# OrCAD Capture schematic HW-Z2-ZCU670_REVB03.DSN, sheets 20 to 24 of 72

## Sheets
20 020 USB 3.0: size Custom
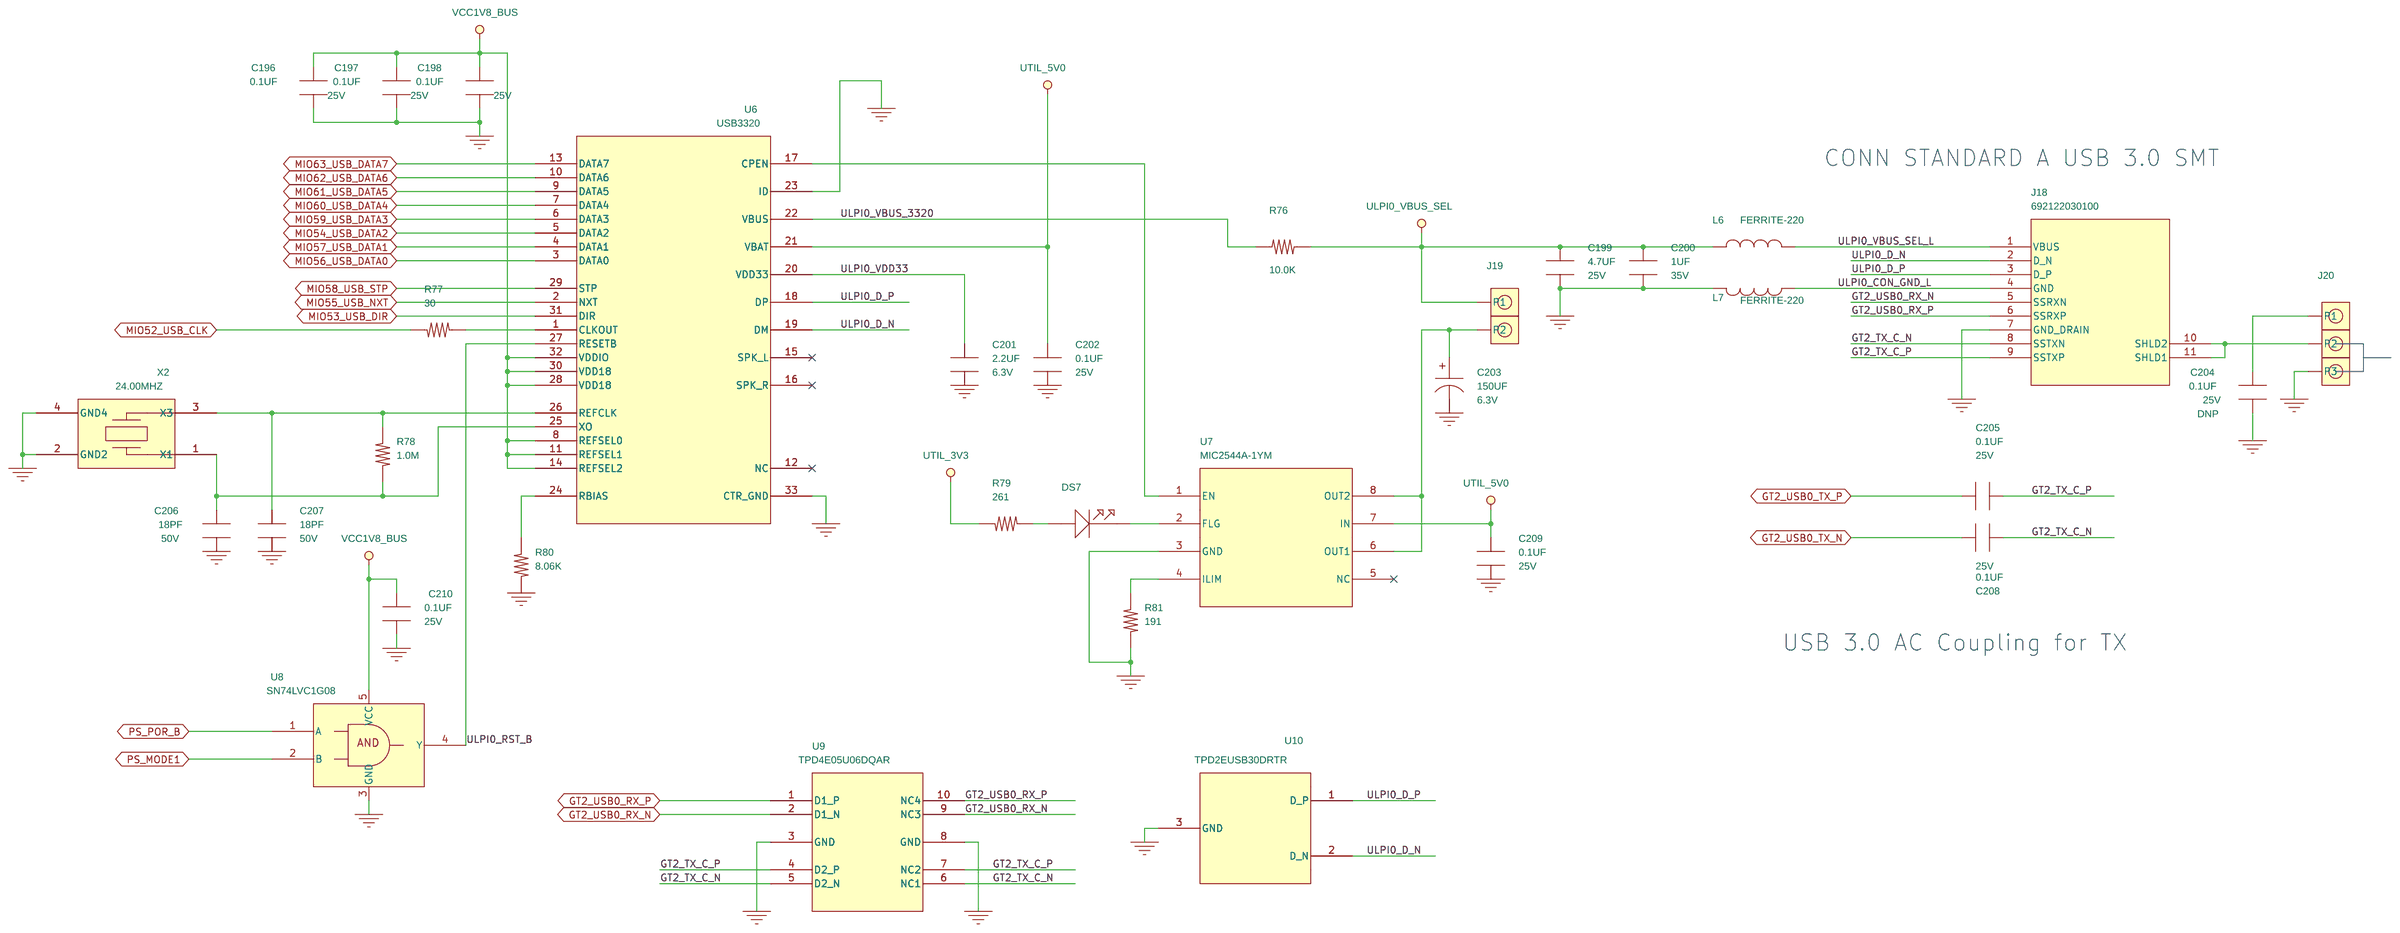
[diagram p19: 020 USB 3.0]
21 021 Dual QSPI: size Custom
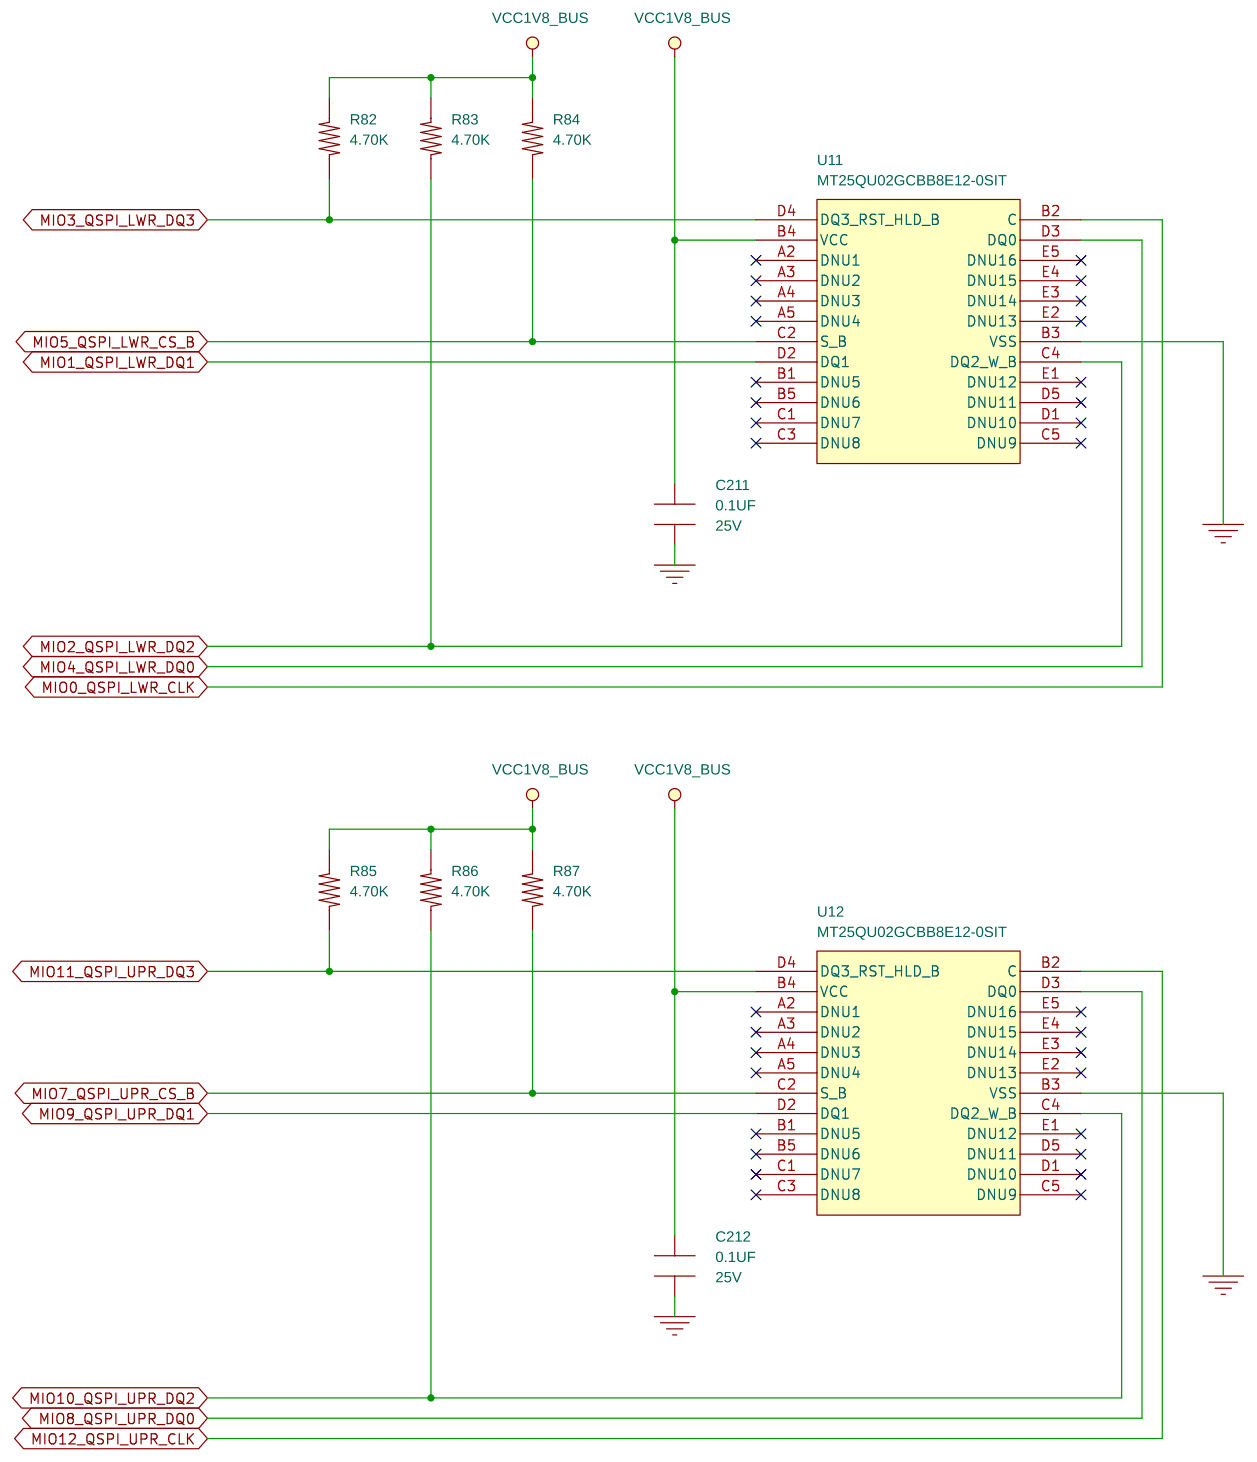
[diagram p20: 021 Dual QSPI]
22 022 I2C0: size Custom
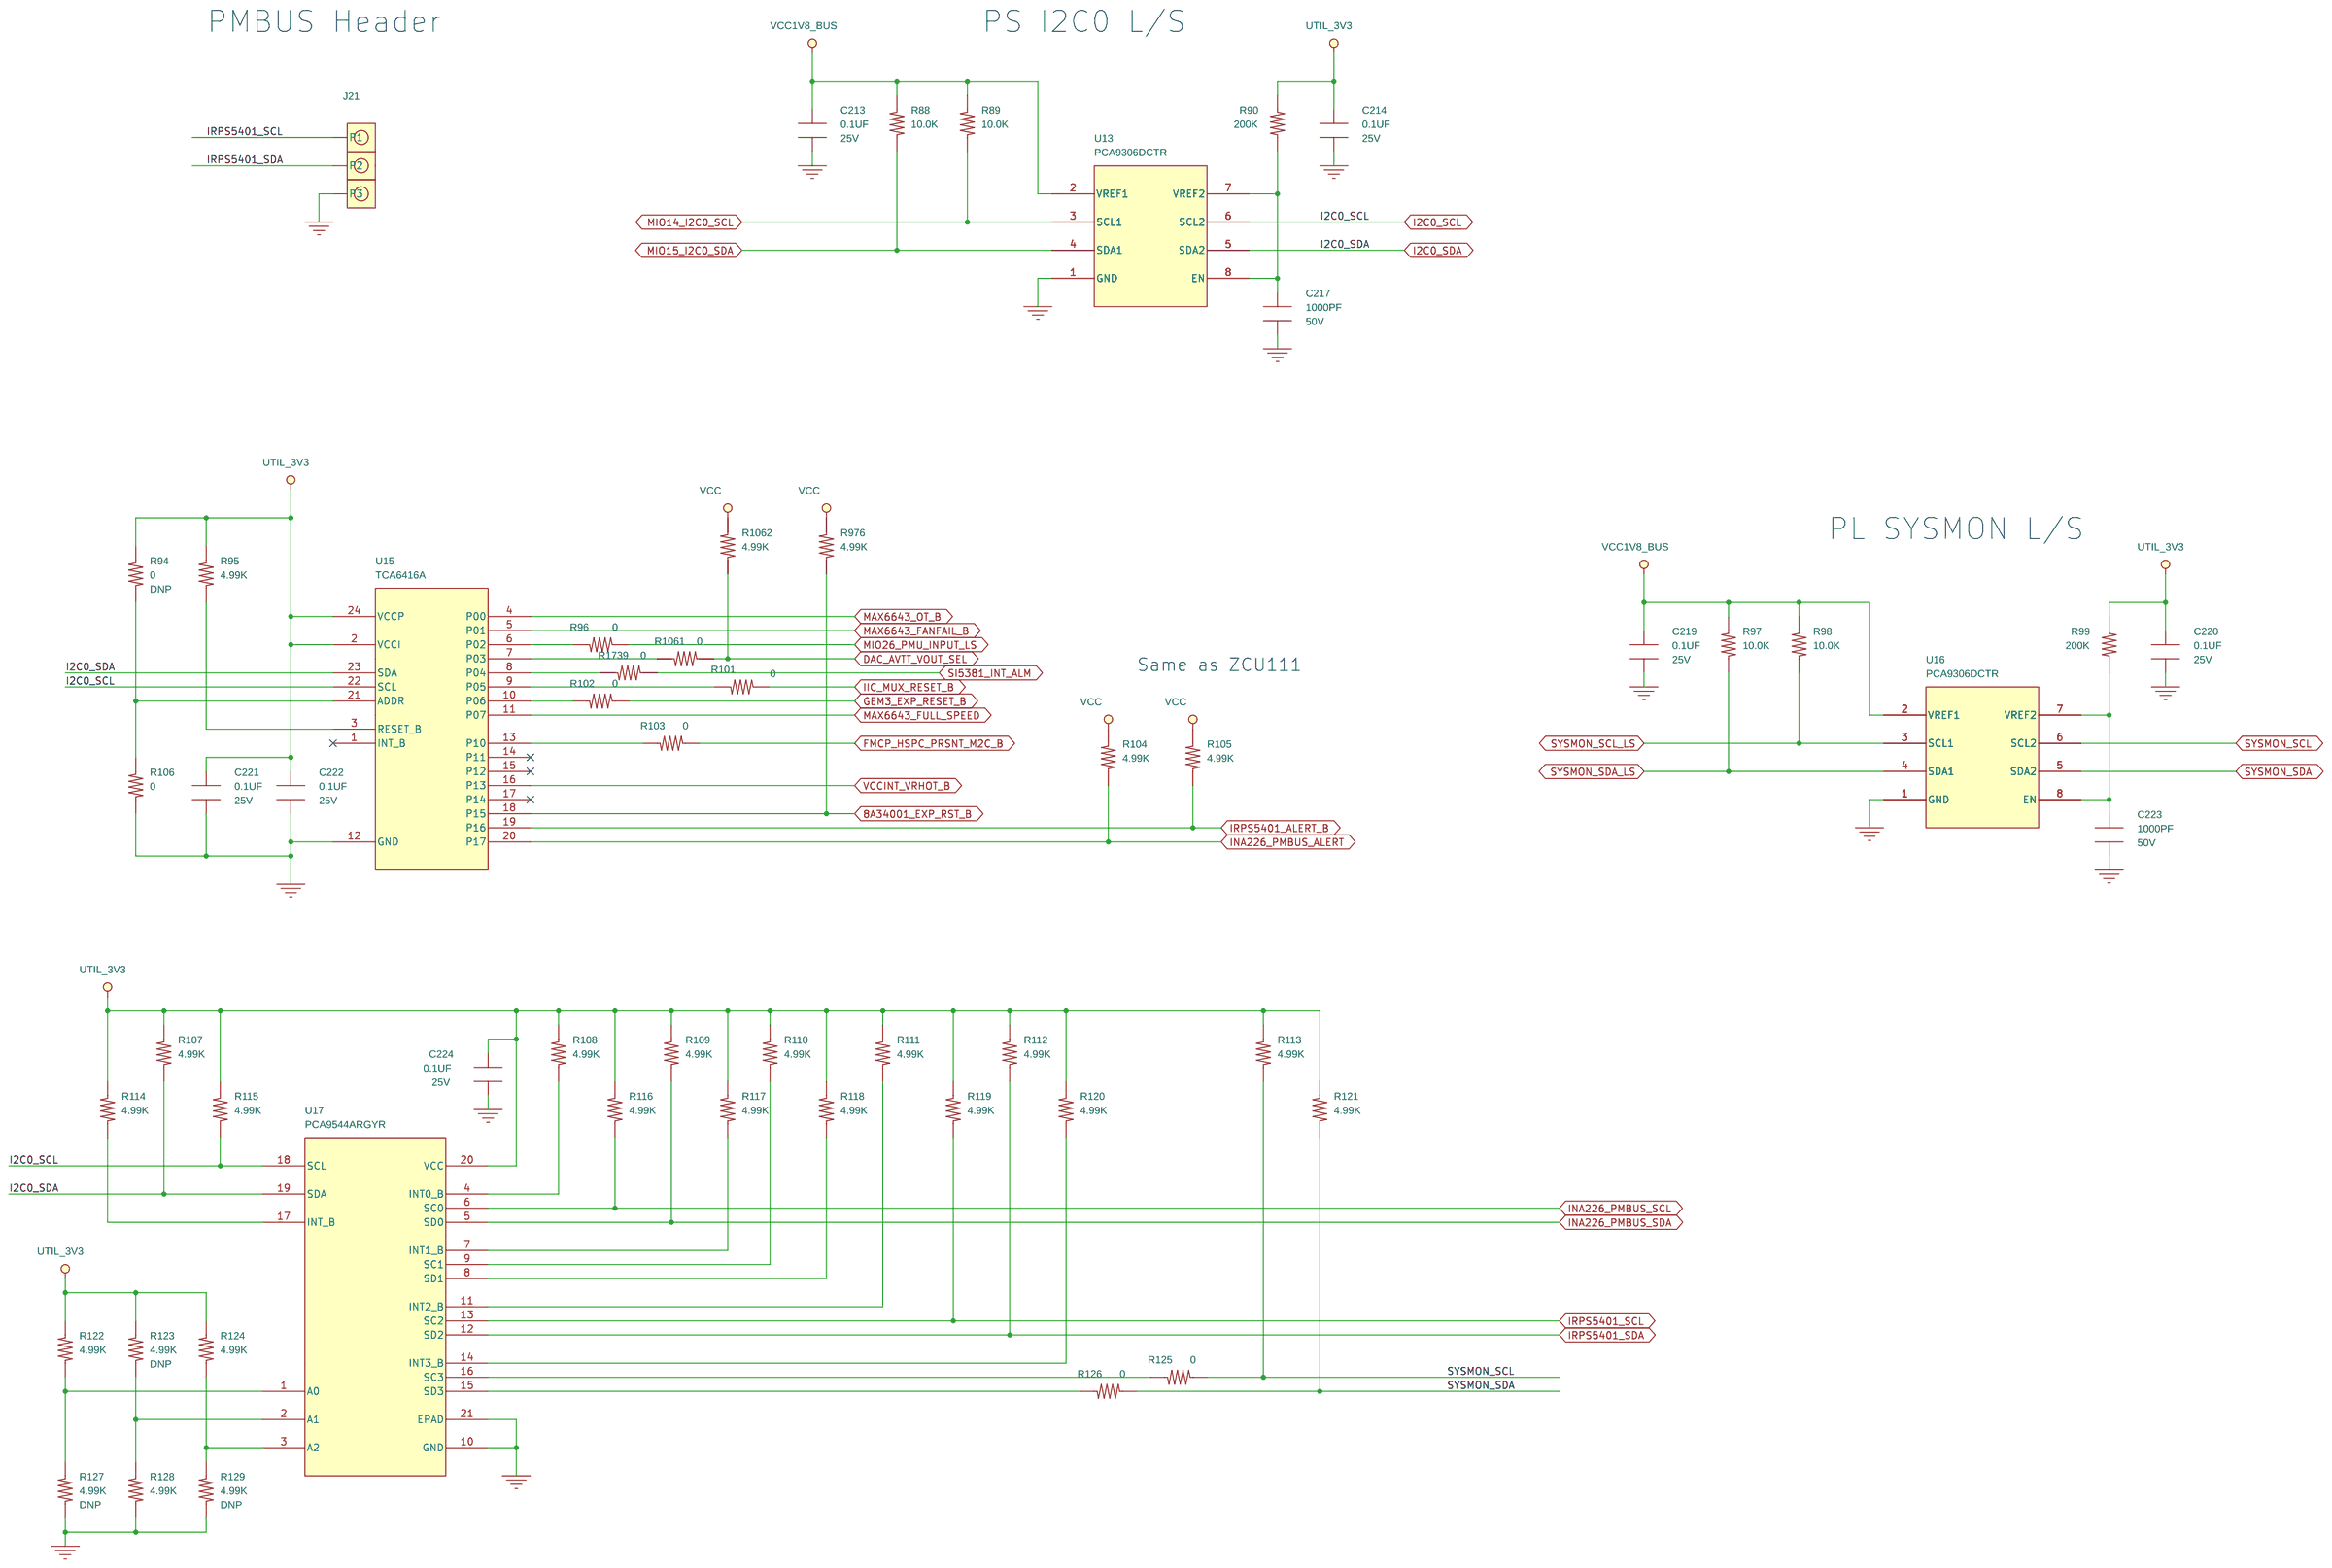
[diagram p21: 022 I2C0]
23 023 I2C1: size Custom
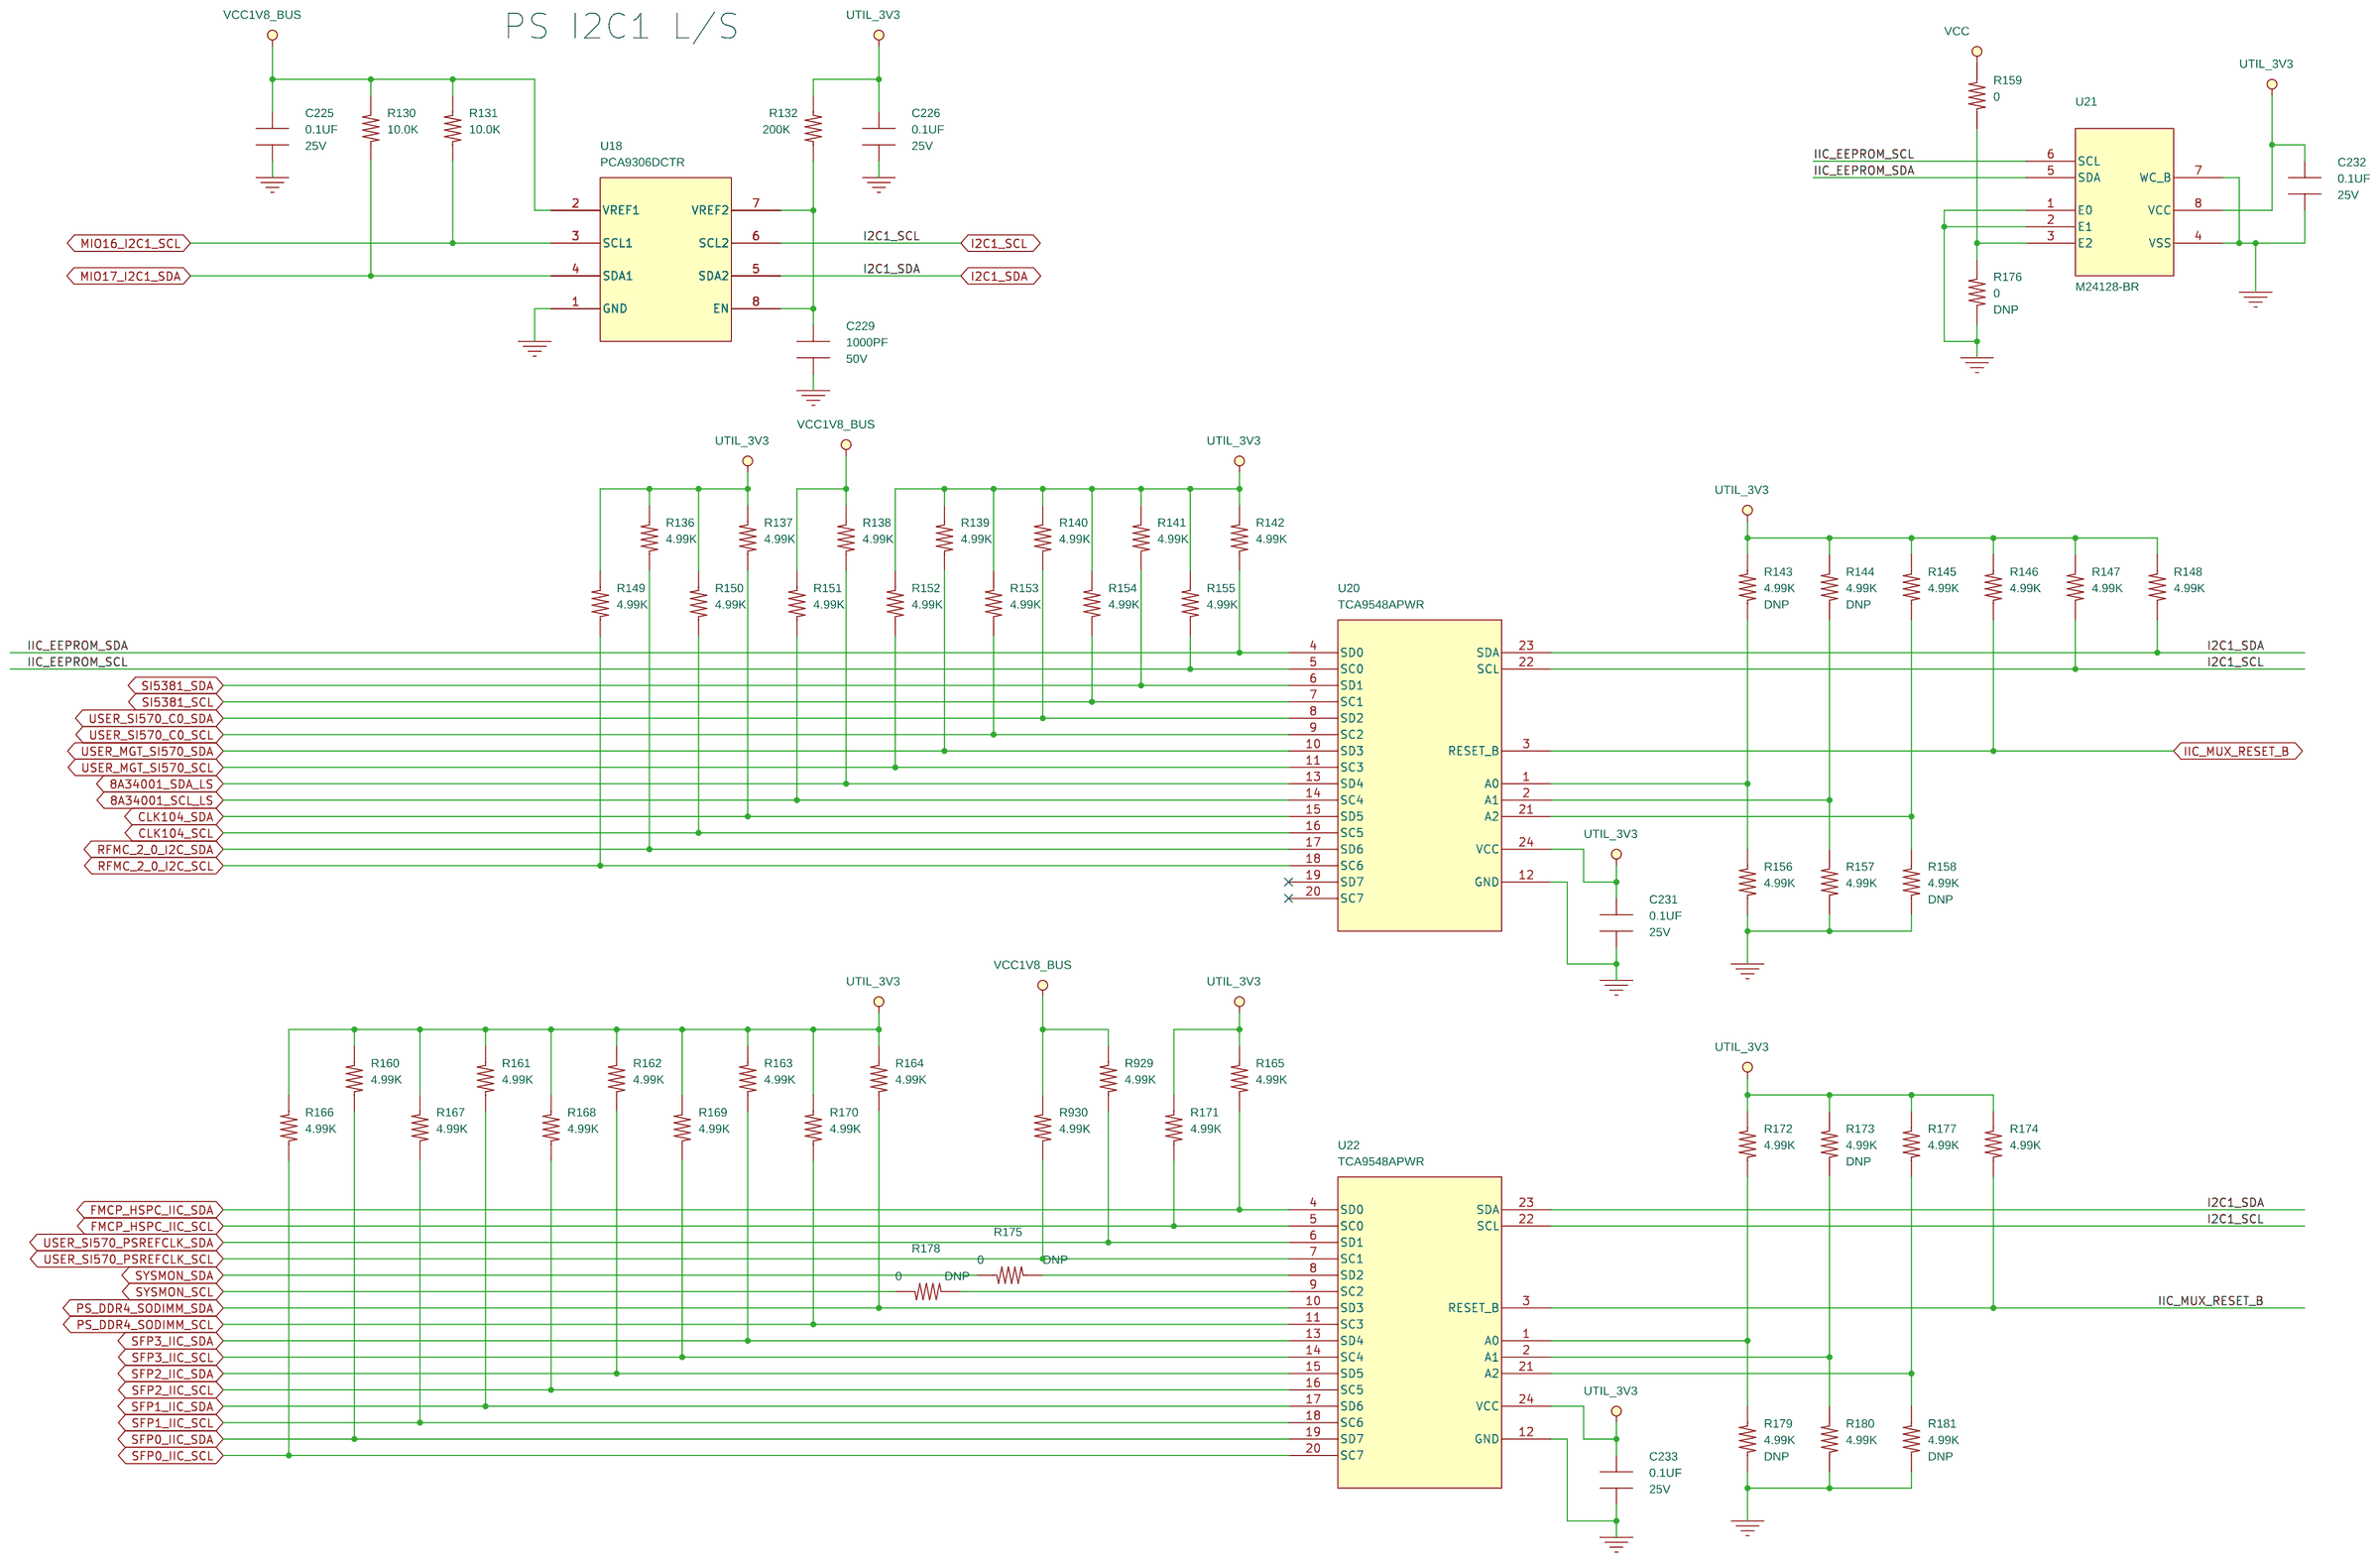
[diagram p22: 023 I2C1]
24 024 SD 3.0: size Custom
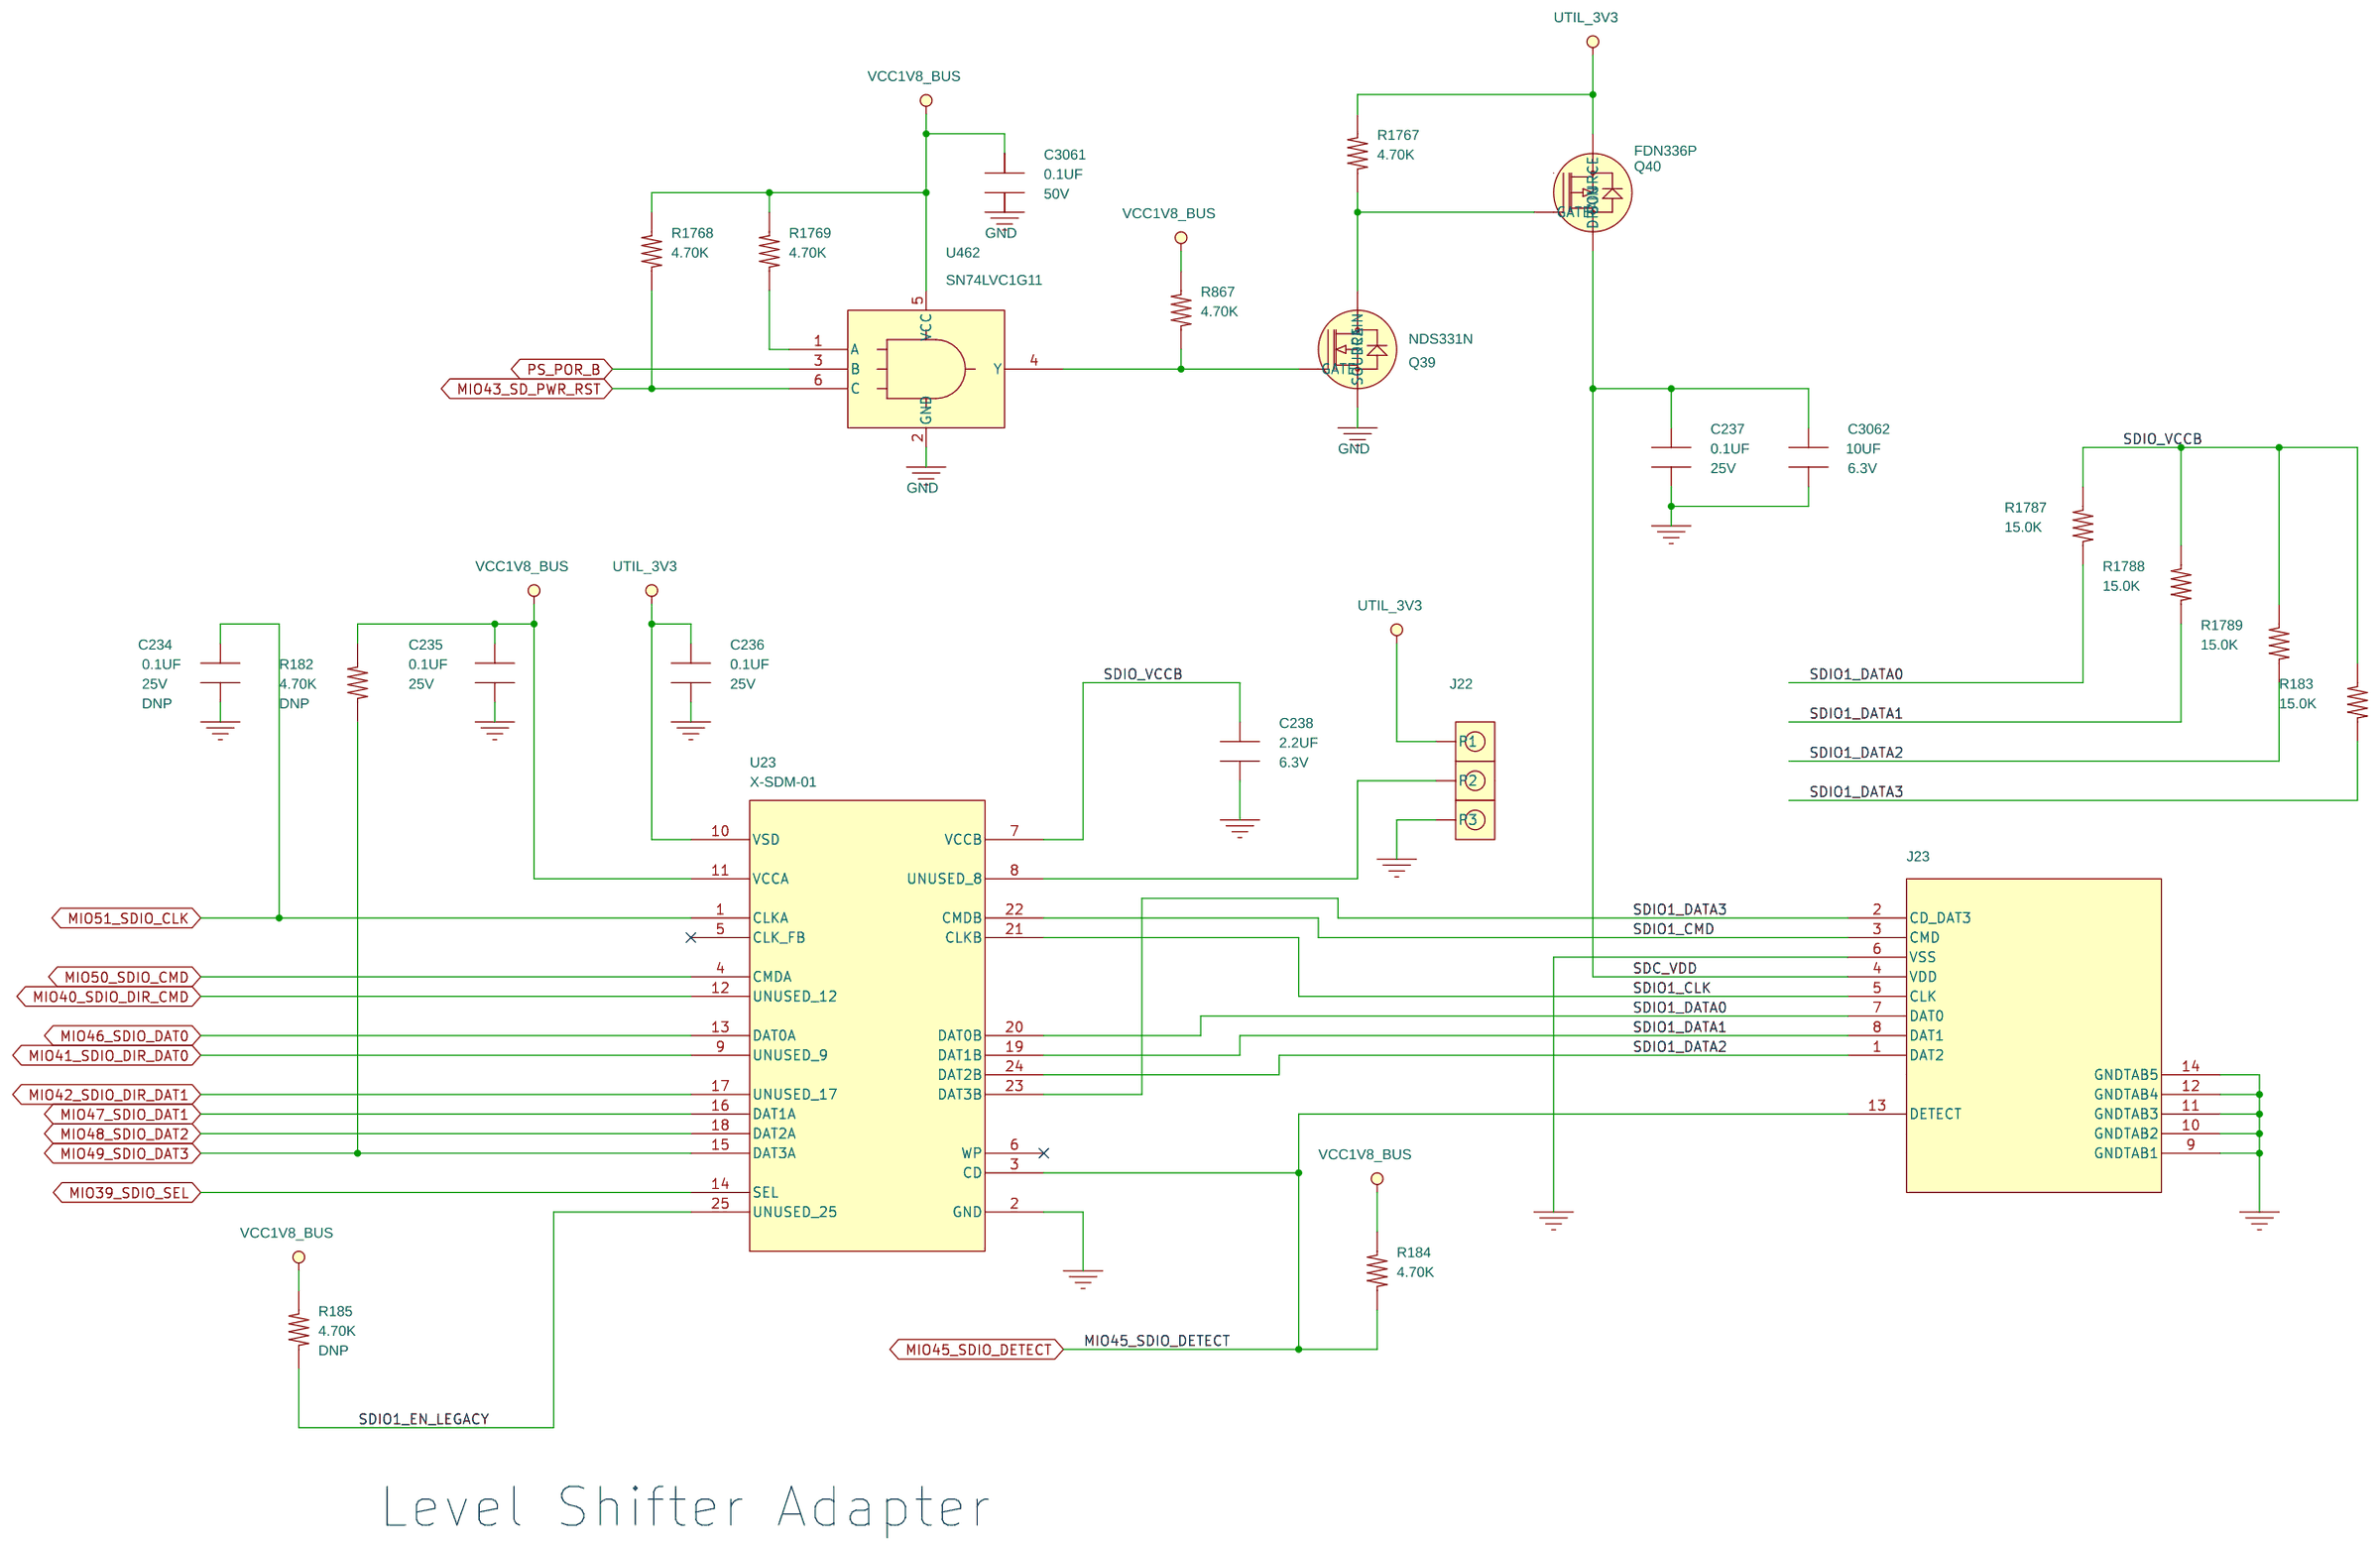
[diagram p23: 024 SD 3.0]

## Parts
sheet 020 USB 3.0
C196  0.1UF  [CAPC100X50X55]
C197  0.1UF  [CAPC100X50X55]
C198  0.1UF  [CAPC100X50X55]
C199  4.7UF  [CAPC160X80X100]
C200  1UF  [CAPC100X50X60]
C201  2.2UF  [CAPC100X50X55]
C202  0.1UF  [CAPC100X50X55]
C203  150UF  [CAPMP730X430X210]
C204  0.1UF  [CAPC100X50X55]
C205  0.1UF  [CAPC100X50X55]
C206  18PF  [CAPC100X50X50]
C207  18PF  [CAPC100X50X50]
C208  0.1UF  [CAPC100X50X55]
C209  0.1UF  [CAPC100X50X55]
C210  0.1UF  [CAPC100X50X55]
DS7  LED-GRN-SMT  [LED_0603]
J18  692122030100  [CON_CNC_692122030100]
J19  HDR_1X2  [HDR_1X2]
J20  HDR_1X3  [HDR_1X3]
L6  FERRITE-220  [INDC160X80X95]
L7  FERRITE-220  [INDC160X80X95]
R76  10.0K  [RESC100X50X40]
R77  30  [RESC100X50X40]
R78  1.0M  [RESC100X50X40]
R79  261  [RESC100X50X40]
R80  8.06K  [RESC100X50X40]
R81  191  [RESC100X50X40]
U6  USB3320  [QFN05P500X500X100_32P_330EP]
U7  MIC2544A-1YM  [SOIC_8]
U8  SN74LVC1G08  [SC70_5]
U9  TPD4E05U06DQAR  [DQA_R_PSON_N10]
U10  TPD2EUSB30DRTR  [DRT_R_PDSO_N3]
X2  24.00MHZ  [XTAL_EPSON_FA238]
sheet 021 Dual QSPI
C211  0.1UF  [CAPC100X50X55]
C212  0.1UF  [CAPC100X50X55]
R82  4.70K  [RESC100X50X40]
R83  4.70K  [RESC100X50X40]
R84  4.70K  [RESC100X50X40]
R85  4.70K  [RESC100X50X40]
R86  4.70K  [RESC100X50X40]
R87  4.70K  [RESC100X50X40]
U11  MT25QU02GCBB8E12-0SIT  [TPBGA_24_5X5]
U12  MT25QU02GCBB8E12-0SIT  [TPBGA_24_5X5]
sheet 022 I2C0
C213  0.1UF  [CAPC100X50X55]
C214  0.1UF  [CAPC100X50X55]
C217  1000PF  [CAPC100X50X55]
C219  0.1UF  [CAPC100X50X55]
C220  0.1UF  [CAPC100X50X55]
C221  0.1UF  [CAPC100X50X55]
C222  0.1UF  [CAPC100X50X55]
C223  1000PF  [CAPC100X50X55]
C224  0.1UF  [CAPC100X50X55]
J21  HDR_1X3  [HDR_1X3]
R88  10.0K  [RESC100X50X40]
R89  10.0K  [RESC100X50X40]
R90  200K  [RESC100X50X40]
R94  0  [RESC100X50X40]
R95  4.99K  [RESC100X50X40]
R96  0  [RESC100X50X40]
R97  10.0K  [RESC100X50X40]
R98  10.0K  [RESC100X50X40]
R99  200K  [RESC100X50X40]
R101  0  [RESC100X50X40]
R102  0  [RESC100X50X40]
R103  0  [RESC100X50X40]
R104  4.99K  [RESC100X50X40]
R105  4.99K  [RESC100X50X40]
R106  0  [RESC100X50X40]
R107  4.99K  [RESC100X50X40]
R108  4.99K  [RESC100X50X40]
R109  4.99K  [RESC100X50X40]
R110  4.99K  [RESC100X50X40]
R111  4.99K  [RESC100X50X40]
R112  4.99K  [RESC100X50X40]
R113  4.99K  [RESC100X50X40]
R114  4.99K  [RESC100X50X40]
R115  4.99K  [RESC100X50X40]
R116  4.99K  [RESC100X50X40]
R117  4.99K  [RESC100X50X40]
R118  4.99K  [RESC100X50X40]
R119  4.99K  [RESC100X50X40]
R120  4.99K  [RESC100X50X40]
R121  4.99K  [RESC100X50X40]
R122  4.99K  [RESC100X50X40]
R123  4.99K  [RESC100X50X40]
R124  4.99K  [RESC100X50X40]
R125  0  [RESC100X50X40]
R126  0  [RESC100X50X40]
R127  4.99K  [RESC100X50X40]
R128  4.99K  [RESC100X50X40]
R129  4.99K  [RESC100X50X40]
R976  4.99K  [RESC100X50X40]
R1061  0  [RESC100X50X40]
R1062  4.99K  [RESC100X50X40]
R1739  0  [RESC100X50X40]
U13  PCA9306DCTR  [DCT_R_PDSO_G8]
U15  TCA6416A  [TSSOP_24]
U16  PCA9306DCTR  [DCT_R_PDSO_G8]
U17  PCA9544ARGYR  [VQFN05P350x450x100_20_300X200]
sheet 023 I2C1
C225  0.1UF  [CAPC100X50X55]
C226  0.1UF  [CAPC100X50X55]
C229  1000PF  [CAPC100X50X55]
C231  0.1UF  [CAPC100X50X55]
C232  0.1UF  [CAPC100X50X55]
C233  0.1UF  [CAPC100X50X55]
R130  10.0K  [RESC100X50X40]
R131  10.0K  [RESC100X50X40]
R132  200K  [RESC100X50X40]
R136  4.99K  [RESC100X50X40]
R137  4.99K  [RESC100X50X40]
R138  4.99K  [RESC100X50X40]
R139  4.99K  [RESC100X50X40]
R140  4.99K  [RESC100X50X40]
R141  4.99K  [RESC100X50X40]
R142  4.99K  [RESC100X50X40]
R143  4.99K  [RESC100X50X40]
R144  4.99K  [RESC100X50X40]
R145  4.99K  [RESC100X50X40]
R146  4.99K  [RESC100X50X40]
R147  4.99K  [RESC100X50X40]
R148  4.99K  [RESC100X50X40]
R149  4.99K  [RESC100X50X40]
R150  4.99K  [RESC100X50X40]
R151  4.99K  [RESC100X50X40]
R152  4.99K  [RESC100X50X40]
R153  4.99K  [RESC100X50X40]
R154  4.99K  [RESC100X50X40]
R155  4.99K  [RESC100X50X40]
R156  4.99K  [RESC100X50X40]
R157  4.99K  [RESC100X50X40]
R158  4.99K  [RESC100X50X40]
R159  0  [RESC100X50X40]
R160  4.99K  [RESC100X50X40]
R161  4.99K  [RESC100X50X40]
R162  4.99K  [RESC100X50X40]
R163  4.99K  [RESC100X50X40]
R164  4.99K  [RESC100X50X40]
R165  4.99K  [RESC100X50X40]
R166  4.99K  [RESC100X50X40]
R167  4.99K  [RESC100X50X40]
R168  4.99K  [RESC100X50X40]
R169  4.99K  [RESC100X50X40]
R170  4.99K  [RESC100X50X40]
R171  4.99K  [RESC100X50X40]
R172  4.99K  [RESC100X50X40]
R173  4.99K  [RESC100X50X40]
R174  4.99K  [RESC100X50X40]
R175  0  [RESC100X50X40]
R176  0  [RESC100X50X40]
R177  4.99K  [RESC100X50X40]
R178  0  [RESC100X50X40]
R179  4.99K  [RESC100X50X40]
R180  4.99K  [RESC100X50X40]
R181  4.99K  [RESC100X50X40]
R929  4.99K  [RESC100X50X40]
R930  4.99K  [RESC100X50X40]
U18  PCA9306DCTR  [DCT_R_PDSO_G8]
U20  TCA9548APWR  [TSSOP_24]
U21  M24128-BR  [TSSOP65P640X120_8]
U22  TCA9548APWR  [TSSOP_24]
sheet 024 SD 3.0
C234  0.1UF  [CAPC100X50X55]
C235  0.1UF  [CAPC100X50X55]
C236  0.1UF  [CAPC100X50X55]
C237  0.1UF  [CAPC100X50X55]
C238  2.2UF  [CAPC100X50X55]
C3061  0.1UF  [CAPC100X50X55]
C3062  10UF  [CAPC100X50X70]
J22  HDR_1X3  [HDR_1X3]
J23  CON_MOL_10P_5025700893  [CON_MOL_10P_5025700893]
Q39  NDS331N  [SOT_23]
Q40  FDN336P  [SOT_23]
R182  4.70K  [RESC100X50X40]
R183  15.0K  [RESC100X50X40]
R184  4.70K  [RESC100X50X40]
R185  4.70K  [RESC100X50X40]
R867  4.70K  [RESC100X50X40]
R1767  4.70K  [RESC100X50X40]
R1768  4.70K  [RESC100X50X40]
R1769  4.70K  [RESC100X50X40]
R1787  15.0K  [RESC100X50X40]
R1788  15.0K  [RESC100X50X40]
R1789  15.0K  [RESC100X50X40]
U23  X-SDM-01  [IP4856CX25_SHIFTER_ADAPTER]
U462  SN74LVC1G11  [SC70_6]

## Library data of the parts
C196-C198 C202 C205 C208-C214 C219-C222 C224-C226 C231-C233 C235-C237 = CAP_NP: Cap Cer 100nF 10% 25V X5R 0402; ALT_SYMBOLS: CAPC100X50X55RND; Agile Part Number: CAP-00068-01; CIP Link: http://xsjbrdwin1/CIP-E/Component/Index/All?pn=100040; Dielectric Type: X5R; OWNER: 4001; PRICE: 0.01; Part Type: CERAMIC; PartType: CERAMIC; ROHS: Yes; Tolerance: 10%; Voltage: 25V; barcode: 100040
C199 = CAP_NP: Cap Cer 4.7uF 10% 25V X5R 0603; ALT_SYMBOLS: 0603; Agile Part Number: CAP-00182-01; CIP Link: http://xsjbrdwin1/CIP-E/Component/Index/All?pn=100220; Dielectric Type: X5R; OWNER: 8251; PRICE: 0.26; Part Type: CERAMIC; PartType: CERAMIC; ROHS: Yes; Tolerance: 10%; Voltage: 25V; barcode: 100220
C200 = CAP_NP: Cap Cer 1uF 10% 35V X5R 0402; ALT_SYMBOLS: CAPC100X50X60RND; Agile Part Number: CAP-00165-01; CIP Link: http://xsjbrdwin1/CIP-E/Component/Index/All?pn=100192; Dielectric Type: X5R; OWNER: 3709; PRICE: 0.04; Part Type: CERAMIC; PartType: CERAMIC; ROHS: Yes; Tolerance: 10%; Voltage: 35V; barcode: 100192
C201 C238 = CAP_NP: Cap Cer 2.2uF 20% 6.3V X5R 0402; Agile Part Number: CAP-00081-01; CIP Link: http://xsjbrdwin1/CIP-E/Component/Index/All?pn=100062; Dielectric Type: X5R; OWNER: 6176; PRICE: 0.06; Part Type: CERAMIC; PartType: CERAMIC; ROHS: Yes; Tolerance: 20%; Voltage: 6.3V; barcode: 100062
C203 = CAP_P: Cap Poly 150uF 20% 6.3V 12mR 7343; Agile Part Number: CAP-00157-01; CIP Link: http://xsjbrdwin1/CIP-E/Component/Index/All?pn=100183; Dielectric Type: SP; ESR: 12mohms; Equivalent Series Resistance: 12mohms; OWNER: 3709; PRICE: 0.68; Part Type: SPCAP; PartType: SPCAP; ROHS: Yes; Tolerance: 20%; Voltage: 6.3V; barcode: 100183
C204 C234 = CAP_NP: Cap Cer 100nF 10% 25V X5R 0402; ALT_SYMBOLS: CAPC100X50X55RND; ASSEMBLY_OPTIONS: DNP; Agile Part Number: CAP-00068-01; CIP Link: http://xsjbrdwin1/CIP-E/Component/Index/All?pn=100040; Dielectric Type: X5R; OWNER: 3709; PRICE: 0; Part Type: CERAMIC; PartType: CERAMIC; ROHS: Yes; Tolerance: 10%; Voltage: 25V; barcode: 100040
C206 C207 = CAP_NP: Cap Cer 18pF 2% 50% C0G 0402; ALT_SYMBOLS: CAPC100X50X50RND; Agile Part Number: CAP-00084-01; CIP Link: http://xsjbrdwin1/CIP-E/Component/Index/All?pn=100065; Dielectric Type: NPO; OWNER: 3709; PRICE: 0; Part Type: CERAMIC; PartType: CERAMIC; ROHS: Yes; Tolerance: 5%; Voltage: 50V; barcode: 100065
DS7 = LED: LED Green Diffused 20mA 5V 570nm 0603; Agile Part Number: DIO-00003-01; Barcode: 300021; CIP Link: http://xsjbrdwin1/CIP-E/Component/Index/All?pn=300021; OWNER: 4001; PRICE: 0.1; Power: 2.2-20MA; ROHS: Yes; Rated Power: 2.2-20MA; Voltage: 2.2V
J18 = 692122030100: Conn Rcpt USB 3.0 Type A RA 9 Pos 1x9 1.25mm P Blue SMT; Agile Part Number: CON-00183-01; Barcode: 400128; CIP Link: http://xsjbrdwin1/CIP-E/Component/Index/All?pn=400128; OWNER: 14196; PRICE: 2.4; Part Type: RECEPTACLE; PartType: RECEPTACLE; Pins: 9PINS; ROHS: Yes
J19 = HDR_1X2: Conn Hdr Male Vert 2 Pos 1x2 2.54mm P Black TH; Agile Part Number: CON-00037-01; Barcode: 390102; CIP Link: http://xsjbrdwin1/CIP-E/Component/Index/All?pn=390102; OWNER: 4001; PRICE: 0.03; Part Type: HEADER; PartType: HEADER; Pins: 2PINS; Pitch: 0.100; ROHS: Yes
J20-J22 = HDR_1X3: Conn Hdr Vert 3 Pos 1x3 2.54mm P Black TH; Agile Part Number: CON-00038-01; Barcode: 390103; CIP Link: http://xsjbrdwin1/CIP-E/Component/Index/All?pn=390103; Part Type: HEADER; Pitch: 0.100; ROHS: Yes
L6 L7 = IND: Bead 220R 25% 2A 50mR 0603; Agile Part Number: IND-00016-01; Barcode: 300010; CIP Link: http://xsjbrdwin1/CIP-E/Component/Index/All?pn=300010; OWNER: 4001; PRICE: 0.02; Part Type: FERRITE; PartType: FERRITE; ROHS: Yes
R76 R88 R89 R97 R98 R130 R131 = RES: Res 10K 1% 1/16W 100PPM 50V 0402; ALT_SYMBOLS: RESC100X50X40RND; Agile Part Number: RES-00030-01; Barcode: 200025; CIP Link: http://xsjbrdwin1/CIP-E/Component/Index/All?pn=200025; OWNER: 4001; PRICE: 0; Part Type: SMT - 1%; PartType: SMT - 1%; Power: 1/10W; ROHS: Yes; Rated Power: 1/16W; Tolerance: 1%; primarykey: 1
R77 = RES: Res 30R 1% 1/16W 100PPM 50V 0402; Agile Part Number: RES-00143-01; Barcode: 200133; CIP Link: http://xsjbrdwin1/CIP-E/Component/Index/All?pn=200133; OWNER: 3709; PRICE: 0; Part Type: SMT - 1%; PartType: SMT - 1%; Power: 1/10W; ROHS: Yes; Rated Power: 1/16W; Tolerance: 1%; primarykey: 93
R78 = RES: Res 1M 5% 1/16W 200PPM 50V 0402; Agile Part Number: RES-00066-01; Barcode: 200013; CIP Link: http://xsjbrdwin1/CIP-E/Component/Index/All?pn=200013; OWNER: 4001; PRICE: 0; Part Type: SMT - 5%; PartType: SMT - 5%; Power: 1/10W; ROHS: Yes; Rated Power: 1/16W; Tolerance: 5%; primarykey: 4
R79 = RES: Res 261R 1% 1/16W 100PPM 50V 0402; ALT_SYMBOLS: RESC100X50X40RND; Agile Part Number: RES-00086-01; Barcode: 200050; CIP Link: http://xsjbrdwin1/CIP-E/Component/Index/All?pn=200050; OWNER: 3501; PRICE: 0; Part Type: SMT - 1%; PartType: SMT - 1%; Power: 1/10W; ROHS: Yes; Rated Power: 1/16W; Tolerance: 1%; primarykey: 60
R80 = RES: Res 8K06 1% 1/16W 100PPM 50V 0402; ALT_SYMBOLS: RESC100X50X40RND; Agile Part Number: RES-00111-01; Barcode: 200083; CIP Link: http://xsjbrdwin1/CIP-E/Component/Index/All?pn=200083; OWNER: 3709; PRICE: 0; Part Type: SMT - 1%; PartType: SMT - 1%; Power: 1/10W; ROHS: Yes; Rated Power: 1/16W; Tolerance: 1%; primarykey: 74
R81 = RES: Res 191R 1% 1/16W 100PPM 50V 0402; Agile Part Number: RES-00267-01; Barcode: 200288; CIP Link: http://xsjbrdwin1/CIP-E/Component/Index/All?pn=200288; OWNER: 6176; PRICE: 0; Part Type: SMT - 1%; PartType: SMT - 1%; Power: 1/16W; ROHS: Yes; Rated Power: 1/16W; Tolerance: 1%; primarykey: 241
U6 = USB3320_QFN32: IC Xcvr USB 2.0 3.3V VQFN-32 ULPI; Agile Part Number: ICS-00089-01; Barcode: 500065; CIP Link: http://xsjbrdwin1/CIP-E/Component/Index/All?pn=500065; Family: USB TRANSCEIVER; Part Type: USB TRANSCEIVER; ROHS: Yes
U7 = MIC2544A_1YM: IC Switch Power 1.5A 5.5V 120mR SOIC-8 High Side; Agile Part Number: ICS-00312-01; Barcode: 500451; CIP Link: http://xsjbrdwin1/CIP-E/Component/Index/All?pn=500451; Family: REGULATOR; Part Type: REGULATOR; ROHS: Yes
U8 = AND_GATE_SINGLE: IC AND Single 2-In 5V 50mA 3.6nSec SC70-5; Agile Part Number: ICS-00094-01; Barcode: 500077; CIP Link: http://xsjbrdwin1/CIP-E/Component/Index/All?pn=500077; Family: LOGIC; Part Type: LOGIC; ROHS: Yes
U9 = TPD4E05U06DQAR: TVS 4-Ch 5.5V 2.5A 40W USON-10 12KV Contact Discharge; Agile Part Number: ICS-00281-01; Barcode: 500416; CIP Link: http://xsjbrdwin1/CIP-E/Component/Index/All?pn=500416; Family: ESD PROTECTOR; Part Type: ESD PROTECTOR; ROHS: Yes
U10 = TPD2EUSB30: TVSD 2-Ch 5.5V 5A 45W SOT-9X3 USB 3.0; Agile Part Number: ICS-00193-01; Barcode: 500259; CIP Link: http://xsjbrdwin1/CIP-E/Component/Index/All?pn=500259; Family: ESD PROTECTOR; Part Type: ESD PROTECTOR; ROHS: Yes
X2 = FA-238A_XTAL: Xtal 24MHz 200uW 50R 18pF 80PPM  3225; Agile Part Number: XTL-00027-01; Barcode: 600067; CIP Link: http://xsjbrdwin1/CIP-E/Component/Index/All?pn=600067; OWNER: 3709; Part Type: CRYSTAL; PartType: CRYSTAL; ROHS: yes
R82-R87 R184 R867 R1767-R1769 = RES: Res 4K7 1% 1/16W 100PPM 50V 0402; ALT_SYMBOLS: RESC100X50X40RND; Agile Part Number: RES-00035-01; Barcode: 200067; CIP Link: http://xsjbrdwin1/CIP-E/Component/Index/All?pn=200067; OWNER: 3670; PRICE: 0.01; Part Type: SMT - 1%; PartType: SMT - 1%; Power: 1/16W; ROHS: Yes; Rated Power: 1/16W; Tolerance: 1%; primarykey: 128
U11 U12 = MT25QU02GCBB8E12-0SIT: IC Flash NOR SPI 2Gb 166MHz 1.8V T-PBGA-24; Agile Part Number: 1310617; Barcode: 510068; CIP Link: http://xsjbrdwin1/CIP-E/Component/Index/All?pn=510068; Family: MEMORY; Part Type: MEMORY; ROHS: YES
C217 C223 C229 = CAP_NP: Cap Cer 1nF 10% 50V X7R 0402; ALT_SYMBOLS: CAPC100X50X55RND; Agile Part Number: CAP-00036-01; CIP Link: http://xsjbrdwin1/CIP-E/Component/Index/All?pn=100013; Dielectric Type: X7R; OWNER: 3709; PRICE: 0; Part Type: CERAMIC; PartType: CERAMIC; ROHS: Yes; Tolerance: 10%; Voltage: 50V; barcode: 100013
R90 R99 R132 = RES: Res 200K 1% 1/16W 100PPM 50V 0402; Agile Part Number: RES-00078-01; Barcode: 200041; CIP Link: http://xsjbrdwin1/CIP-E/Component/Index/All?pn=200041; OWNER: 10460; PRICE: 0; Part Type: SMT - 1%; PartType: SMT - 1%; Power: 1/10W; ROHS: Yes; Rated Power: 1/10W; Tolerance: 1%; primarykey: 98
R94 R175 R176 R178 = RES: Res 0R 50mR 1A 0402; ALT_SYMBOLS: RESC100X50X40RND; ASSEMBLY_OPTIONS: DNP; Agile Part Number: RES-00010-01; Barcode: 200012; CIP Link: http://xsjbrdwin1/CIP-E/Component/Index/All?pn=200012; OWNER: 3709; Part Type: SMT - 5%; PartType: SMT - DNP; Power: DNP; ROHS: Yes; Tolerance: 5%; primarykey: 73
R95 R104 R105 R107-R122 R124 R128 R136-R142 R145-R157 R160-R172 R174 R177 R180 R929 R930 R976 R1062 = RES: Res 4K99 1% 1/16W 100PPM 50V 0402; ALT_SYMBOLS: RESC100X50X40RND; Agile Part Number: RES-00004-01; Barcode: 200072; CIP Link: http://xsjbrdwin1/CIP-E/Component/Index/All?pn=200072; OWNER: 10460; PRICE: 0; Part Type: SMT - 1%; PartType: SMT - 1%; Power: 1/10W; ROHS: Yes; Rated Power: 1/16W; Tolerance: 1%; primarykey: 157
R96 R101-R103 R106 R125 R126 R159 R1061 R1739 = RES: Res 0R 50mR 1A 0402; ALT_SYMBOLS: RESC100X50X40RND; Agile Part Number: RES-00010-01; Barcode: 200012; CIP Link: http://xsjbrdwin1/CIP-E/Component/Index/All?pn=200012; OWNER: 4001; PRICE: 0.01; Part Type: SMT - 5%; PartType: SMT - 5%; Power: 1/10W; ROHS: Yes; Tolerance: 5%; primarykey: 13
R123 R127 R129 R143 R144 R158 R173 R179 R181 = RES: Res 4K99 1% 1/16W 100PPM 50V 0402; ALT_SYMBOLS: RESC100X50X40RND; ASSEMBLY_OPTIONS: DNP; Agile Part Number: RES-00004-01; Barcode: 200072; CIP Link: http://xsjbrdwin1/CIP-E/Component/Index/All?pn=200072; OWNER: 3709; PRICE: 0; Part Type: SMT - 1%; PartType: SMT - DNP; Power: DNP; ROHS: Yes; Rated Power: 1/16W; Tolerance: 1%; primarykey: 73
U13 U16 U18 = PCA9306DCTR: IC Lvl Trans Dual Bidir I2C/SM Bus 1.2-5.5V SSOP-8; Agile Part Number: ICS-00172-01; Barcode: 500219; CIP Link: http://xsjbrdwin1/CIP-E/Component/Index/All?pn=500219; Family: LEVEL TRANSLATOR; Part Type: LEVEL TRANSLATOR; ROHS: Yes
U15 = TCA6416A: IC Exp GPIO 16 Bit I2C 400KHz TSSOP-24; Agile Part Number: ICS-00125-01; Barcode: 500124; CIP Link: http://xsjbrdwin1/CIP-E/Component/Index/All?pn=500124; Family: INTERFACE DATA TRANSMISSION; Part Type: INTERFACE DATA TRANSMISSION; ROHS: Yes
U17 = PCA9544A: IC Mux I2C 1 to 4 400KHz VQFN-20; Agile Part Number: ICS-00162-01; Barcode: 500203; CIP Link: http://xsjbrdwin1/CIP-E/Component/Index/All?pn=500203; Family: MULTIPLEXER; Part Type: MULTIPLEXER; ROHS: Yes
U20 U22 = TCA9548A: IC MUX I2C 1 to 8 400KHz TSSOP-24 with Reset; Agile Part Number: ICS-00220-01; Barcode: 500297; CIP Link: http://xsjbrdwin1/CIP-E/Component/Index/All?pn=500297; Family: MULTIPLEXER; Part Type: MULTIPLEXER; ROHS: Yes
U21 = M24128-BR: IC EEPROM 128Kb 16Kx8b I2C 1MHz 5V TSSOP-8; Agile Part Number: ICS-00355-01; Barcode: 500546; CIP Link: http://xsjbrdwin1/CIP-E/Component/Index/All?pn=500546; Part Type: MEMORY
C3061 = CAP_NP: Cap Cer 100nF 10% 50V X7R 0402; ALT_SYMBOLS: CAPC100X50X55RND; Agile Part Number: CAP-00022-01; CIP Link: http://xsjbrdwin1/CIP-E/Component/Index/All?pn=100170; Dielectric Type: X7R; OWNER: 4001; PRICE: 0.01; Part Type: CERAMIC; PartType: CERAMIC; ROHS: Yes; Tolerance: 10%; Voltage: 50V; barcode: 100170
C3062 = CAP_NP: Cap Cer 10uF 20%  6.3V X6S 0402; ALT_SYMBOLS: CAPC100X50X55RND; Agile Part Number: CAP-00035-01; Barcode: 100268; CIP Link: http://xsjbrdwin1/CIP-E/Component/Index/All?pn=100268; Dielectric Type: X6S; Part Type: CERAMIC; Tolerance: 20%; Voltage: 6.3V
J23 = 5025700893: Conn Rcpt Skt Micro SD Card RA 8 Pos 1x8 1.1mm P Black SMT Push-Push; Agile Part Number: CON-00148-01; Barcode: 400081; CIP Link: http://xsjbrdwin1/CIP-E/Component/Index/All?pn=400081; OWNER: 3709; PRICE: 2.17; Part Type: SD-SLOT; PartType: SD-SLOT; Pins: 14PINS; Pitch: 1.1MM; ROHS: Yes
Q39 = FET-3PIN: MOSFET N-Ch 20V 1.3A 160mR SSOT-3; Agile Part Number: TRN-00012-01; Barcode: 500100; CIP Link: http://xsjbrdwin1/CIP-E/Component/Index/All?pn=500100; OWNER: 4001; PRICE: 0.12; Part Type: FET; PartType: FET; Power: 460MW; ROHS: Yes; Rated Power: 460MW; Rated Voltage: 20V
Q40 = NDS336P: MOSFET P-Ch 20V 1.3A 200mR SSOT-3; Agile Part Number: TRN-00011-01; Barcode: 500098; CIP Link: http://xsjbrdwin1/CIP-E/Component/Index/All?pn=500098; Part Type: FET; Rated Power: 460MW; Rated Voltage: 20V
R182 R185 = RES: Res 4K7 1% 1/16W 100PPM 50V 0402; ALT_SYMBOLS: RESC100X50X40RND; ASSEMBLY_OPTIONS: DNP; Agile Part Number: RES-00035-01; Barcode: 200067; CIP Link: http://xsjbrdwin1/CIP-E/Component/Index/All?pn=200067; OWNER: 3670; PRICE: 0.01; Part Type: SMT - 1%; PartType: SMT - 1%; Power: 1/16W; ROHS: Yes; Rated Power: 1/16W; Tolerance: 1%; primarykey: 128
R183 R1787-R1789 = RES: Res 15K 1% 1/16W 100PPM 50V 0402; ALT_SYMBOLS: (0402,C402-25,RESC100X50X40L25NRND); Agile Part Number: RES-00047-01; Barcode: 200226; CIP Link: http://xsjbrdwin1/CIP-E/Component/Index/All?pn=200226; Part Type: SMT - 1%; Rated Power: 1/16W; Tolerance: 1%
U23 = X-SDM-01: NVT4857UK_SHIFTER_ADAPTER; Agile Part Number: 043-05055-01; Barcode: 50000162; CIP Link: http://xsjbrdwin1/CIP-E/Component/Index/All?pn=50000162; Part Type: ADAPTER
U462 = SN74LVC1G11: IC AND Single 3-In 4.6nSec SC70-6; Agile Part Number: ICS-00115-01; Barcode: 500108; CIP Link: http://xsjbrdwin1/CIP-E/Component/Index/All?pn=500108; Family: LOGIC; Part Type: LOGIC; ROHS: Yes; Voltage: 1.65V-5.5V

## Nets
GND: C196.2 C197.2 C198.2 C199.2 C200.2 C201.2 C202.2 C203.2 C204.2 C206.2 C207.2 C209.2 C210.2 C211.2 C212.2 C213.2 C214.2 C217.2 C219.2 C220.2 C221.2 C222.2 C223.2 C224.2 C225.2 C226.2 C229.2 C231.2 C232.2 C233.2 C234.2 C235.2 C236.2 C237.2 C238.2 C3061.2 C3062.2 J18.7(GND_DRAIN) J20.3(P3) J21.3(P3) J22.3(P3) J23.6(VSS) J23.9(GNDTAB1) J23.10(GNDTAB2) J23.11(GNDTAB3) J23.12(GNDTAB4) J23.14(GNDTAB5) L7.1 Q39.2(SOURCE) R80.2 R81.2 R106.2 R127.2 R128.2 R129.2 R156.2 R157.2 R158.2 R176.2 R179.2 R180.2 R181.2 U6.23(ID) U6.33(CTR_GND) U7.3(GND) U8.3(GND) U9.3(GND) U9.8(GND) U10.3(GND) U11.B3(VSS) U12.B3(VSS) U13.1(GND) U15.12(GND) U16.1(GND) U17.10(GND) U17.21(EPAD) U18.1(GND) U20.12(GND) U21.1(E0) U21.2(E1) U21.4(VSS) U21.7(WC_B) U22.12(GND) U23.2(GND) U462.2(GND) X2.2(GND2) X2.4(GND4) ; also on sheet 3 4 5 7 8 9 10 11 12 13 14 16 17 18 19 25 26 27 28 32 33 34 35 36 37 38 39 40 41 42 43 44 45 46 47 48 49 50 51 52 53 54 55 56 57 58 59 60 61 62 63 64 65 66 67 68 69 70 71 72
VCC1V8_BUS: C196.1 C197.1 C198.1 C210.1 C211.1 C212.1 C213.1 C219.1 C225.1 C235.1 C3061.1 R82.1 R83.1 R84.1 R85.1 R86.1 R87.1 R88.1 R89.1 R97.1 R98.1 R130.1 R131.1 R138.1 R151.1 R182.1 R184.1 R185.1 R867.1 R929.1 R930.1 R1768.1 R1769.1 U6.8(REFSEL0) U6.11(REFSEL1) U6.14(REFSEL2) U6.28(VDD18) U6.30(VDD18) U6.32(VDDIO) U8.5(VCC) U11.B4(VCC) U12.B4(VCC) U13.2(VREF1) U16.2(VREF1) U18.2(VREF1) U23.11(VCCA) U462.5(VCC) ; also on sheet 4 9 10 12 25 26 27 34 36 37 38 39 42 52 61 62 64
VCCINT_VRHOT_B: U15.16(P13) ; also on sheet 44
8A34001_EXP_RST_B: R976.2 U15.18(P15) ; also on sheet 34
8A34001_SCL_LS: R151.2 U20.14(SC4) ; also on sheet 34
8A34001_SDA_LS: R138.2 U20.13(SD4) ; also on sheet 34
CLK104_SCL: R150.2 U20.16(SC5) ; also on sheet 64
CLK104_SDA: R137.2 U20.15(SD5) ; also on sheet 64
DAC_AVTT_VOUT_SEL: R1061.2 R1062.2 ; also on sheet 55
FMCP_HSPC_IIC_SCL: R171.2 U22.5(SC0) ; also on sheet 28
FMCP_HSPC_IIC_SDA: R165.2 U22.4(SD0) ; also on sheet 28
FMCP_HSPC_PRSNT_M2C_B: R103.2 ; also on sheet 28 30 31
GEM3_EXP_RESET_B: R102.2 ; also on sheet 26
GT2_TX_C_N: C208.2 J18.8(SSTXN) U9.5(D2_N) U9.6(NC1)
GT2_TX_C_P: C205.2 J18.9(SSTXP) U9.4(D2_P) U9.7(NC2)
GT2_USB0_RX_N: J18.5(SSRXN) U9.2(D1_N) U9.9(NC3) ; also on sheet 12
GT2_USB0_RX_P: J18.6(SSRXP) U9.1(D1_P) U9.10(NC4) ; also on sheet 12
GT2_USB0_TX_N: C208.1 ; also on sheet 12
GT2_USB0_TX_P: C205.1 ; also on sheet 12
I2C0_SCL: R115.2 U13.6(SCL2) U15.22(SCL) U17.18(SCL) ; also on sheet 27
I2C0_SDA: R107.2 U13.5(SDA2) U15.23(SDA) U17.19(SDA) ; also on sheet 27
I2C1_SCL: R147.2 U18.6(SCL2) U20.22(SCL) U22.22(SCL) ; also on sheet 27
I2C1_SDA: R148.2 U18.5(SDA2) U20.23(SDA) U22.23(SDA) ; also on sheet 27
IIC_EEPROM_SCL: R155.2 U20.5(SC0) U21.6(SCL)
IIC_EEPROM_SDA: R142.2 U20.4(SD0) U21.5(SDA)
IIC_MUX_RESET_B: R101.2 R146.2 R174.2 U20.3(RESET_B) U22.3(RESET_B)
INA226_PMBUS_ALERT: R104.2 U15.20(P17) ; also on sheet 45 51 53 54 55 56
INA226_PMBUS_SCL: R116.2 U17.6(SC0) ; also on sheet 45 51 53 54 55 56
INA226_PMBUS_SDA: R109.2 U17.5(SD0) ; also on sheet 45 51 53 54 55 56
IRPS5401_ALERT_B: R105.2 U15.19(P16) ; also on sheet 44 47 49 50 51 52
IRPS5401_SCL: J21.1(P1) R119.2 U17.13(SC2) ; also on sheet 44 47 49 50 51 52
IRPS5401_SDA: J21.2(P2) R112.2 U17.12(SD2) ; also on sheet 44 47 49 50 51 52
MAX6643_FANFAIL_B: U15.5(P01) ; also on sheet 43
MAX6643_FULL_SPEED: U15.11(P07) ; also on sheet 43
MAX6643_OT_B: U15.4(P00) ; also on sheet 43
MIO0_QSPI_LWR_CLK: U11.B2(C) ; also on sheet 9
MIO1_QSPI_LWR_DQ1: U11.D2(DQ1) ; also on sheet 9
MIO2_QSPI_LWR_DQ2: R83.2 U11.C4(DQ2_W_B) ; also on sheet 9
MIO3_QSPI_LWR_DQ3: R82.2 U11.D4(DQ3_RST_HLD_B) ; also on sheet 9
MIO4_QSPI_LWR_DQ0: U11.D3(DQ0) ; also on sheet 9
MIO5_QSPI_LWR_CS_B: R84.2 U11.C2(S_B) ; also on sheet 9
MIO7_QSPI_UPR_CS_B: R87.2 U12.C2(S_B) ; also on sheet 9
MIO8_QSPI_UPR_DQ0: U12.D3(DQ0) ; also on sheet 9
MIO9_QSPI_UPR_DQ1: U12.D2(DQ1) ; also on sheet 9
MIO10_QSPI_UPR_DQ2: R86.2 U12.C4(DQ2_W_B) ; also on sheet 9
MIO11_QSPI_UPR_DQ3: R85.2 U12.D4(DQ3_RST_HLD_B) ; also on sheet 9
MIO12_QSPI_UPR_CLK: U12.B2(C) ; also on sheet 9
MIO14_I2C0_SCL: R89.2 U13.3(SCL1) ; also on sheet 9
MIO15_I2C0_SDA: R88.2 U13.4(SDA1) ; also on sheet 9
MIO16_I2C1_SCL: R131.2 U18.3(SCL1) ; also on sheet 9
MIO17_I2C1_SDA: R130.2 U18.4(SDA1) ; also on sheet 9
MIO26_PMU_INPUT_LS: R96.2 ; also on sheet 25
MIO39_SDIO_SEL: U23.14(SEL) ; also on sheet 9
MIO40_SDIO_DIR_CMD: U23.12(UNUSED) ; also on sheet 9
MIO41_SDIO_DIR_DAT0: U23.9(UNUSED) ; also on sheet 9
MIO42_SDIO_DIR_DAT1: U23.17(UNUSED) ; also on sheet 9
MIO43_SD_PWR_RST: R1768.2 U462.6(C) ; also on sheet 9
MIO45_SDIO_DETECT: J23.13(DETECT) R184.2 U23.3(CD) ; also on sheet 9
MIO46_SDIO_DAT0: U23.13(DAT0A) ; also on sheet 9
MIO47_SDIO_DAT1: U23.16(DAT1A) ; also on sheet 9
MIO48_SDIO_DAT2: U23.18(DAT2A) ; also on sheet 9
MIO49_SDIO_DAT3: R182.2 U23.15(DAT3A) ; also on sheet 9
MIO50_SDIO_CMD: U23.4(CMDA) ; also on sheet 9
MIO51_SDIO_CLK: C234.1 U23.1(CLKA) ; also on sheet 9
MIO52_USB_CLK: R77.1 ; also on sheet 9
MIO53_USB_DIR: U6.31(DIR) ; also on sheet 9
MIO54_USB_DATA2: U6.5(DATA2) ; also on sheet 9
MIO55_USB_NXT: U6.2(NXT) ; also on sheet 9
MIO56_USB_DATA0: U6.3(DATA0) ; also on sheet 9
MIO57_USB_DATA1: U6.4(DATA1) ; also on sheet 9
MIO58_USB_STP: U6.29(STP) ; also on sheet 9
MIO59_USB_DATA3: U6.6(DATA3) ; also on sheet 9
MIO60_USB_DATA4: U6.7(DATA4) ; also on sheet 9
MIO61_USB_DATA5: U6.9(DATA5) ; also on sheet 9
MIO62_USB_DATA6: U6.10(DATA6) ; also on sheet 9
MIO63_USB_DATA7: U6.13(DATA7) ; also on sheet 9
PS_DDR4_SODIMM_SCL: R170.2 U22.11(SC3) ; also on sheet 40
PS_DDR4_SODIMM_SDA: R164.2 U22.10(SD3) ; also on sheet 40
PS_MODE1: U8.2(B) ; also on sheet 10
PS_POR_B: U8.1(A) U462.3(B) ; also on sheet 10 25 26
RFMC_2_0_I2C_SCL: R149.2 U20.18(SC6) ; also on sheet 61
RFMC_2_0_I2C_SDA: R136.2 U20.17(SD6) ; also on sheet 61
SDC_VDD: C237.1 C3062.1 J23.4(VDD) Q40.3(DRAIN)
SDIO1_CLK: J23.5(CLK) U23.21(CLKB)
SDIO1_CMD: J23.3(CMD) U23.22(CMDB)
SDIO1_DATA0: J23.7(DAT0) R1787.2 U23.20(DAT0B)
SDIO1_DATA1: J23.8(DAT1) R1788.2 U23.19(DAT1B)
SDIO1_DATA2: J23.1(DAT2) R1789.2 U23.24(DAT2B)
SDIO1_DATA3: J23.2(CD_DAT3) R183.2 U23.23(DAT3B)
SDIO1_EN_LEGACY: R185.2 U23.25(UNUSED)
SDIO_VCCB: C238.1 R183.1 R1787.1 R1788.1 R1789.1 U23.7(VCCB)
SFP0_IIC_SCL: R166.2 U22.20(SC7) ; also on sheet 33
SFP0_IIC_SDA: R160.2 U22.19(SD7) ; also on sheet 33
SFP1_IIC_SCL: R167.2 U22.18(SC6) ; also on sheet 33
SFP1_IIC_SDA: R161.2 U22.17(SD6) ; also on sheet 33
SFP2_IIC_SCL: R168.2 U22.16(SC5) ; also on sheet 33
SFP2_IIC_SDA: R162.2 U22.15(SD5) ; also on sheet 33
SFP3_IIC_SCL: R169.2 U22.14(SC4) ; also on sheet 33
SFP3_IIC_SDA: R163.2 U22.13(SD4) ; also on sheet 33
SI5381_INT_ALM: R1739.2 ; also on sheet 36
SI5381_SCL: R154.2 U20.7(SC1) ; also on sheet 36
SI5381_SDA: R141.2 U20.6(SD1) ; also on sheet 36
SYSMON_SCL: R113.2 R125.2 R178.1 U16.6(SCL2)
SYSMON_SCL_LS: R98.2 U16.3(SCL1) ; also on sheet 5
SYSMON_SDA: R121.2 R126.2 R175.1 U16.5(SDA2)
SYSMON_SDA_LS: R97.2 U16.4(SDA1) ; also on sheet 5
ULPI0_CON_GND_L: J18.4(GND) L7.2
ULPI0_D_N: J18.2(D_N) U6.19(DM) U10.2(D_N)
ULPI0_D_P: J18.3(D_P) U6.18(DP) U10.1(D_P)
ULPI0_RST_B: U6.27(RESETB) U8.4(Y)
ULPI0_VBUS_3320: R76.1 U6.22(VBUS)
ULPI0_VBUS_SEL: C199.1 C200.1 J19.1(P1) L6.1 R76.2
ULPI0_VBUS_SEL_L: J18.1(VBUS) L6.2
ULPI0_VDD33: C201.1 U6.20(VDD33)
USER_MGT_SI570_SCL: R152.2 U20.11(SC3) ; also on sheet 42
USER_MGT_SI570_SDA: R139.2 U20.10(SD3) ; also on sheet 42
USER_SI570_C0_SCL: R153.2 U20.9(SC2) ; also on sheet 42
USER_SI570_C0_SDA: R140.2 U20.8(SD2) ; also on sheet 42
USER_SI570_PSREFCLK_SCL: R930.2 U22.7(SC1) ; also on sheet 42
USER_SI570_PSREFCLK_SDA: R929.2 U22.6(SD1) ; also on sheet 42
UTIL_3V3: C214.1 C220.1 C221.1 C222.1 C224.1 C226.1 C231.1 C232.1 C233.1 C236.1 J22.1(P1) Q40.2(SOURCE) R79.1 R90.1 R94.1 R95.1 R99.1 R104.1 R105.1 R107.1 R108.1 R109.1 R110.1 R111.1 R112.1 R113.1 R114.1 R115.1 R116.1 R117.1 R118.1 R119.1 R120.1 R121.1 R122.1 R123.1 R124.1 R132.1 R136.1 R137.1 R139.1 R140.1 R141.1 R142.1 R143.1 R144.1 R145.1 R146.1 R147.1 R148.1 R149.1 R150.1 R152.1 R153.1 R154.1 R155.1 R159.1 R160.1 R161.1 R162.1 R163.1 R164.1 R165.1 R166.1 R167.1 R168.1 R169.1 R170.1 R171.1 R172.1 R173.1 R174.1 R177.1 R976.1 R1062.1 R1767.1 U15.2(VCCI) U15.24(VCCP) U17.20(VCC) U20.24(VCC) U21.8(VCC) U22.24(VCC) U23.10(VSD) ; also on sheet 9 10 25 26 27 28 29 30 31 33 34 36 37 40 42 43 44 45 47 49 51 53 54 55 56 57 59 60 61 64
UTIL_5V0: C202.1 C209.1 U6.21(VBAT) U7.7(IN) ; also on sheet 44 45 48 53 54 55 58 60 62 64 71 72
N17812915: C206.1 R78.2 U6.25(XO) X2.1(X1)
N18045548: R117.2 U17.7(INT1_B)
N18723863: R96.1 U15.6(P02)
N19217553: R159.2 R176.1 U21.3(E2)
N20081015: C223.1 R99.2 U16.7(VREF2) U16.8(EN)
N21038095: C203.1 J19.2(P2) U7.6(OUT1) U7.8(OUT2)
N21226446: R77.2 U6.1(CLKOUT)
N21226496: R80.1 U6.24(RBIAS)
N21227026: C207.1 R78.1 U6.26(REFCLK) X2.3(X3)
N21227060: U6.17(CPEN) U7.1(EN)
N21227258: R81.1 U7.4(ILIM)
N21227284: DS7.1 U7.2(FLG)
N21227292: DS7.2 R79.2
N21231835: J18.10(SHLD2) J18.11(SHLD1) J20.2(P2)
N21232118: C204.1 J20.1(P1)
N21242523: C217.1 R90.2 U13.7(VREF2) U13.8(EN)
N21248463: R94.2 R106.1 U15.21(ADDR)
N21248475: R95.2 U15.3(RESET_B)
N21248593: R101.1 U15.9(P05)
N21248607: R102.1 U15.10(P06)
N21250167: R103.1 U15.13(P10)
N21251566: R114.2 U17.17(INT_B)
N21252729: R120.2 U17.14(INT3_B)
N21252734: R125.1 U17.16(SC3)
N21252739: R126.1 U17.15(SD3)
N21253003: R124.2 R129.1 U17.3(A2)
N21253232: R123.2 R128.1 U17.2(A1)
N21253243: R122.2 R127.1 U17.1(A0)
N21254674: C229.1 R132.2 U18.7(VREF2) U18.8(EN)
N21255742: R145.2 R158.1 U20.21(A2)
N21255745: R144.2 R157.1 U20.2(A1)
N21255748: R143.2 R156.1 U20.1(A0)
N21259253: R177.2 R181.1 U22.21(A2)
N21259255: R173.2 R180.1 U22.2(A1)
N21259257: R172.2 R179.1 U22.1(A0)
N21261520: R175.2 U22.8(SD2)
N21261523: R178.2 U22.9(SC2)
N21288341: J22.2(P2) U23.8(UNUSED)
N22702430: R108.2 U17.4(INT0_B)
N22702609: R111.2 U17.11(INT2_B)
N22703022: R110.2 U17.9(SC1)
N22703027: R118.2 U17.8(SD1)
N26786236: R1061.1 U15.7(P03)
N31358166: R1739.1 U15.8(P04)
N31780508: Q39.3(DRAIN) Q40.1(GATE) R1767.2
N31780568: Q39.1(GATE) R867.2 U462.4(Y)
N31808681: R1769.2 U462.1(A)

Not connected (* = marked no-connect by the designer): U6 12(NC)* 15(SPK_L)* 16(SPK_R)*; U7 5(NC)*; U11 A2(DNU1)* A3(DNU2)* A4(DNU3)* A5(DNU4)* B1(DNU5)* B5(DNU6)* C1(DNU7)* C3(DNU8)* C5(DNU9)* D1(DNU10)* D5(DNU11)* E1(DNU12)* E2(DNU13)* E3(DNU14)* E4(DNU15)* E5(DNU16)*; U12 A2(DNU1)* A3(DNU2)* A4(DNU3)* A5(DNU4)* B1(DNU5)* B5(DNU6)* C1(DNU7)* C3(DNU8)* C5(DNU9)* D1(DNU10)* D5(DNU11)* E1(DNU12)* E2(DNU13)* E3(DNU14)* E4(DNU15)* E5(DNU16)*; U15 1(INT_B)* 14(P11)* 15(P12)* 17(P14)*; U20 19(SD7)* 20(SC7)*; U23 5(CLK_FB)* 6(WP)*

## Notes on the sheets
sheet 20
- CONN STANDARD A USB 3.0 SMT
- USB 3.0 AC Coupling for TX
sheet 22
- PMBUS Header
- PS I2C0 L/S
- PL SYSMON L/S
- Same as ZCU111
sheet 23
- PS I2C1 L/S
sheet 24
- Level Shifter Adapter
